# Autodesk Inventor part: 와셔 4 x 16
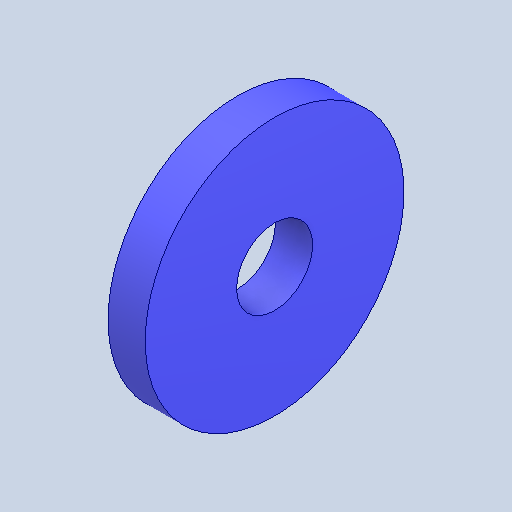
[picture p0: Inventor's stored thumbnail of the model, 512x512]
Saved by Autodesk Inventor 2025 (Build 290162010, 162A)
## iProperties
Created: 2024-07
Part Number: 와셔 4 x 16
Material: 강철, 연강
Description: 미터법 평면 와셔
Document SubType Name: Modeling
Designer: 계정
Density: 7.85 g/cm^3
Appearance: 기본값
Author: jhkim
Sending System: Autodesk Inventor 2025
Preprocessor: ST-DEVELOPER v20
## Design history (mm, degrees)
feature "Solid1"
node "솔리드1"
